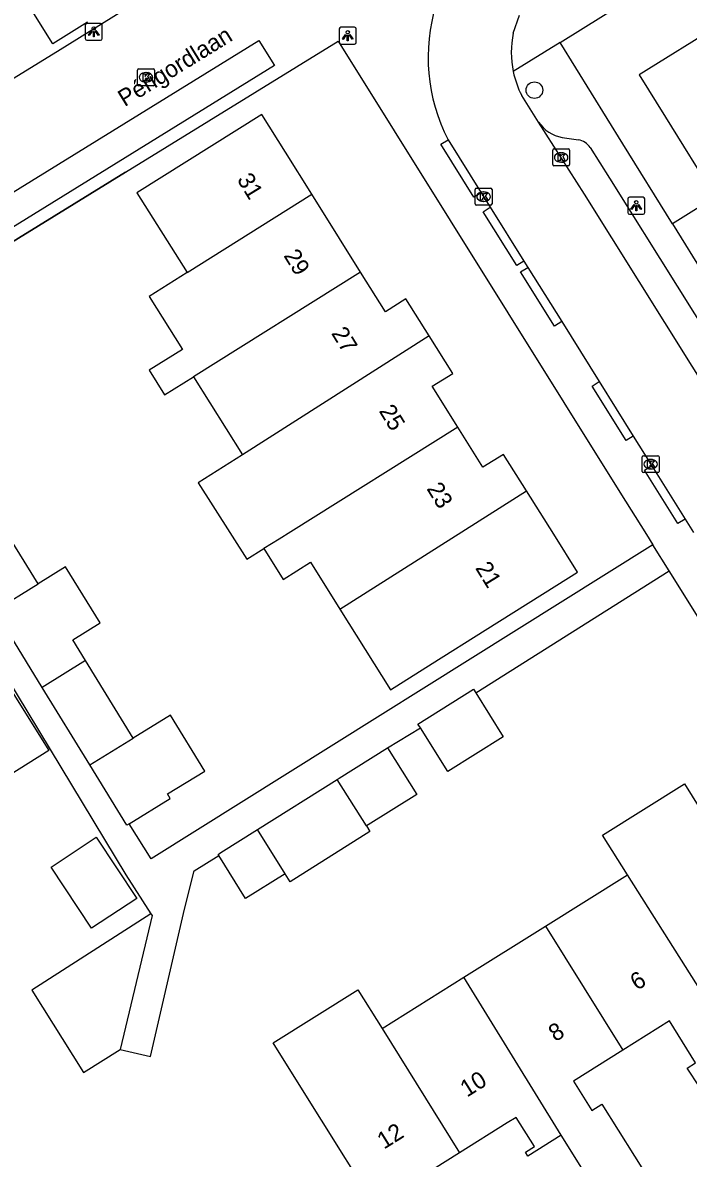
# Model space of a CAD drawing. Extents: x 157767 to 159171, y 387842 to 389425.
# Drawn here: x 158346.5 to 158385.9, y 388132.7 to 388199.8 of the extents above; entities that cross this region are included whole.
import ezdxf

# ---------------------------------------------------------------- set-up
doc = ezdxf.new("R2010")
doc.units = 0
for name, color, linetype in [('IMGEO_Boom', 7, 'Continuous'), ('IMGEO_Kolk', 7, 'Continuous'), ('IMGEO_Lichtpunt', 7, 'Continuous'), ('IMGEO_Muur', 7, 'Continuous'), ('IMGEO_Openbare_ruimte_label', 7, 'Continuous'), ('IMGEO_Pand', 7, 'Continuous'), ('IMGEO_Pand_nummerreeks', 7, 'Continuous'), ('IMGEO_Rijbaan_lokaal_open', 7, 'Continuous'), ('IMGEO_Voetpad_open', 7, 'Continuous')]:
    doc.layers.add(name, color=color, linetype=linetype)

msp = doc.modelspace()

# ---------------------------------------------------------------- linework, layer by layer
at = {"layer": 'IMGEO_Boom'}
msp.add_circle((158376.764, 388195.808), 0.489, dxfattribs=at)
at = {"layer": 'IMGEO_Kolk'}
for p, q in [((158353.327, 388196.137), (158353.327, 388196.989)), ((158353.402, 388197.063), (158354.254, 388197.063)), ((158354.328, 388196.989), (158354.328, 388196.137)), ((158353.838, 388196.283), (158353.813, 388196.283)), ((158353.815, 388196.843), (158353.84, 388196.843)), ((158354.254, 388196.063), (158353.402, 388196.063)), ((158377.846, 388191.409), (158377.846, 388192.261)), ((158377.921, 388192.335), (158378.773, 388192.335)), ((158378.847, 388192.261), (158378.847, 388191.409)), ((158378.357, 388191.555), (158378.332, 388191.555)), ((158378.334, 388192.115), (158378.359, 388192.115)), ((158378.773, 388191.335), (158377.921, 388191.335)), ((158373.261, 388189.093), (158373.261, 388189.945)), ((158373.336, 388190.019), (158374.188, 388190.019)), ((158373.749, 388189.799), (158373.774, 388189.799)), ((158374.262, 388189.945), (158374.262, 388189.093)), ((158374.188, 388189.019), (158373.336, 388189.019)), ((158373.772, 388189.239), (158373.747, 388189.239)), ((158383.133, 388173.299), (158383.133, 388174.151)), ((158383.208, 388174.225), (158384.06, 388174.225)), ((158384.134, 388174.151), (158384.134, 388173.299)), ((158383.644, 388173.445), (158383.619, 388173.445)), ((158383.621, 388174.005), (158383.646, 388174.005)), ((158384.06, 388173.225), (158383.208, 388173.225))]:
    msp.add_line(p, q, dxfattribs=at)
for points in [[(158353.327, 388196.137), (158353.327, 388196.989)], [(158353.402, 388197.063), (158354.254, 388197.063)], [(158354.328, 388196.989), (158354.328, 388196.137)], [(158353.648, 388196.763), (158353.771, 388196.763), (158353.771, 388196.612), (158353.901, 388196.763), (158354.065, 388196.763), (158353.919, 388196.612), (158354.072, 388196.363), (158353.92, 388196.363), (158353.835, 388196.527), (158353.771, 388196.46), (158353.771, 388196.363), (158353.648, 388196.363), (158353.648, 388196.763)], [(158354.254, 388196.063), (158353.402, 388196.063)], [(158377.846, 388191.409), (158377.846, 388192.261)], [(158377.921, 388192.335), (158378.773, 388192.335)], [(158378.847, 388192.261), (158378.847, 388191.409)], [(158378.167, 388192.035), (158378.29, 388192.035), (158378.29, 388191.884), (158378.42, 388192.035), (158378.584, 388192.035), (158378.438, 388191.884), (158378.591, 388191.635), (158378.439, 388191.635), (158378.354, 388191.799), (158378.29, 388191.732), (158378.29, 388191.635), (158378.167, 388191.635), (158378.167, 388192.035)], [(158378.773, 388191.335), (158377.921, 388191.335)], [(158373.261, 388189.093), (158373.261, 388189.945)], [(158373.336, 388190.019), (158374.188, 388190.019)], [(158373.582, 388189.719), (158373.705, 388189.719), (158373.705, 388189.568), (158373.835, 388189.719), (158373.999, 388189.719), (158373.853, 388189.568), (158374.006, 388189.319), (158373.854, 388189.319), (158373.769, 388189.483), (158373.705, 388189.416), (158373.705, 388189.319), (158373.582, 388189.319), (158373.582, 388189.719)], [(158374.262, 388189.945), (158374.262, 388189.093)], [(158374.188, 388189.019), (158373.336, 388189.019)], [(158383.133, 388173.299), (158383.133, 388174.151)], [(158383.208, 388174.225), (158384.06, 388174.225)], [(158384.134, 388174.151), (158384.134, 388173.299)], [(158383.454, 388173.925), (158383.577, 388173.925), (158383.577, 388173.774), (158383.707, 388173.925), (158383.871, 388173.925), (158383.725, 388173.774), (158383.878, 388173.525), (158383.726, 388173.525), (158383.641, 388173.689), (158383.577, 388173.622), (158383.577, 388173.525), (158383.454, 388173.525), (158383.454, 388173.925)], [(158384.06, 388173.225), (158383.208, 388173.225)]]:
    msp.add_lwpolyline(points, dxfattribs=at)
for centre, start, end in [((158353.404, 388196.987), 91.55205, 178.44795), ((158353.404, 388196.987), 91.55205, 178.44795), ((158354.252, 388196.987), 1.55205, 88.44795), ((158354.252, 388196.987), 1.55205, 88.44795), ((158353.404, 388196.139), 181.55205, 268.44795), ((158353.404, 388196.139), 181.55205, 268.44795), ((158354.252, 388196.139), 271.55205, 358.44795), ((158354.252, 388196.139), 271.55205, 358.44795), ((158377.923, 388192.259), 91.55205, 178.44795), ((158377.923, 388192.259), 91.55205, 178.44795), ((158378.771, 388192.259), 1.55205, 88.44795), ((158378.771, 388192.259), 1.55205, 88.44795), ((158377.923, 388191.411), 181.55205, 268.44795), ((158377.923, 388191.411), 181.55205, 268.44795), ((158378.771, 388191.411), 271.55205, 358.44795), ((158378.771, 388191.411), 271.55205, 358.44795), ((158373.338, 388189.943), 91.55205, 178.44795), ((158373.338, 388189.943), 91.55205, 178.44795), ((158374.186, 388189.943), 1.55205, 88.44795), ((158374.186, 388189.943), 1.55205, 88.44795), ((158373.338, 388189.095), 181.55205, 268.44795), ((158373.338, 388189.095), 181.55205, 268.44795), ((158374.186, 388189.095), 271.55205, 358.44795), ((158374.186, 388189.095), 271.55205, 358.44795), ((158383.21, 388174.149), 91.55205, 178.44795), ((158383.21, 388174.149), 91.55205, 178.44795), ((158384.058, 388174.149), 1.55205, 88.44795), ((158384.058, 388174.149), 1.55205, 88.44795), ((158383.21, 388173.301), 181.55205, 268.44795), ((158383.21, 388173.301), 181.55205, 268.44795), ((158384.058, 388173.301), 271.55205, 358.44795), ((158384.058, 388173.301), 271.55205, 358.44795)]:
    msp.add_arc(centre, 0.0765, start, end, dxfattribs=at)
for centre, major_axis, ratio, start_param, end_param in [((158353.814, 388196.563), (-0.387, 0.002), 0.722429, 4.712389, 7.853982), ((158353.839, 388196.563), (-0.39, 0.002), 0.717154, 1.570796, 4.712389), ((158378.333, 388191.835), (-0.387, 0.002), 0.722429, 4.712389, 7.853982), ((158378.358, 388191.835), (-0.39, 0.002), 0.717154, 1.570796, 4.712389), ((158373.748, 388189.519), (-0.387, 0.002), 0.722429, 4.712389, 7.853982), ((158373.773, 388189.519), (-0.39, 0.002), 0.717154, 1.570796, 4.712389), ((158383.62, 388173.725), (-0.387, 0.002), 0.722429, 4.712389, 7.853982), ((158383.645, 388173.725), (-0.39, 0.002), 0.717154, 1.570796, 4.712389)]:
    msp.add_ellipse(centre, major_axis=major_axis, ratio=ratio, start_param=start_param, end_param=end_param, dxfattribs=at)
at = {"layer": 'IMGEO_Lichtpunt'}
for p, q in [((158350.237, 388199.656), (158350.237, 388198.849)), ((158350.237, 388199.656), (158350.237, 388198.849)), ((158351.139, 388199.751), (158350.331, 388199.751)), ((158351.139, 388199.751), (158350.331, 388199.751)), ((158351.233, 388198.849), (158351.233, 388199.656)), ((158351.233, 388198.849), (158351.233, 388199.656)), ((158365.239, 388199.428), (158365.239, 388198.621)), ((158365.239, 388199.428), (158365.239, 388198.621)), ((158366.141, 388199.523), (158365.333, 388199.523)), ((158366.141, 388199.523), (158365.333, 388199.523)), ((158366.235, 388198.621), (158366.235, 388199.428)), ((158366.235, 388198.621), (158366.235, 388199.428)), ((158350.331, 388198.755), (158351.139, 388198.755)), ((158350.331, 388198.755), (158351.139, 388198.755)), ((158365.333, 388198.527), (158366.141, 388198.527)), ((158365.333, 388198.527), (158366.141, 388198.527)), ((158383.185, 388189.481), (158382.377, 388189.481)), ((158383.185, 388189.481), (158382.377, 388189.481)), ((158382.283, 388189.386), (158382.283, 388188.579)), ((158382.283, 388189.386), (158382.283, 388188.579)), ((158383.279, 388188.579), (158383.279, 388189.386)), ((158383.279, 388188.579), (158383.279, 388189.386)), ((158382.377, 388188.485), (158383.185, 388188.485)), ((158382.377, 388188.485), (158383.185, 388188.485))]:
    msp.add_line(p, q, dxfattribs=at)
for points in [[(158350.611, 388199.32), (158350.65, 388199.292), (158350.462, 388199.03), (158350.424, 388199.057), (158350.611, 388199.32)], [(158350.713, 388199.272), (158350.76, 388199.272), (158350.76, 388198.95), (158350.713, 388198.95), (158350.713, 388199.272)], [(158350.823, 388199.292), (158350.861, 388199.319), (158351.048, 388199.057), (158351.009, 388199.029), (158350.823, 388199.292)], [(158365.613, 388199.092), (158365.652, 388199.064), (158365.464, 388198.802), (158365.426, 388198.829), (158365.613, 388199.092)], [(158365.715, 388199.044), (158365.762, 388199.044), (158365.762, 388198.722), (158365.715, 388198.722), (158365.715, 388199.044)], [(158365.825, 388199.064), (158365.863, 388199.091), (158366.05, 388198.829), (158366.011, 388198.801), (158365.825, 388199.064)], [(158382.657, 388189.05), (158382.696, 388189.022), (158382.508, 388188.76), (158382.47, 388188.787), (158382.657, 388189.05)], [(158382.759, 388189.002), (158382.806, 388189.002), (158382.806, 388188.68), (158382.759, 388188.68), (158382.759, 388189.002)], [(158382.869, 388189.022), (158382.907, 388189.049), (158383.094, 388188.787), (158383.055, 388188.759), (158382.869, 388189.022)]]:
    msp.add_lwpolyline(points, dxfattribs=at)
for centre in [(158350.736, 388199.454), (158365.738, 388199.226), (158382.782, 388189.184)]:
    msp.add_circle(centre, 0.0994, dxfattribs=at)
for centre, start, end in [((158350.331, 388199.656), 90, 180), ((158350.331, 388199.656), 90, 180), ((158351.139, 388199.656), 0, 90), ((158351.139, 388199.656), 0, 90), ((158365.333, 388199.428), 90, 180), ((158365.333, 388199.428), 90, 180), ((158366.141, 388199.428), 0, 90), ((158366.141, 388199.428), 0, 90), ((158350.331, 388198.849), 180, 270), ((158350.331, 388198.849), 180, 270), ((158351.139, 388198.849), 270, 0), ((158351.139, 388198.849), 270, 360), ((158365.333, 388198.621), 180, 270), ((158365.333, 388198.621), 180, 270), ((158366.141, 388198.621), 270, 0), ((158366.141, 388198.621), 270, 360), ((158382.377, 388189.386), 90, 180), ((158382.377, 388189.386), 90, 180), ((158383.185, 388189.386), 0, 90), ((158383.185, 388189.386), 0, 90), ((158382.377, 388188.579), 180, 270), ((158382.377, 388188.579), 180, 270), ((158383.185, 388188.579), 270, 0), ((158383.185, 388188.579), 270, 360)]:
    msp.add_arc(centre, 0.0946, start, end, dxfattribs=at)
at = {"layer": 'IMGEO_Muur'}
msp.add_lwpolyline([(158352.615, 388190.965), (158339.034, 388182.597)], dxfattribs=at)
at = {"layer": 'IMGEO_Pand'}
for points in [[(158350.367, 388199.826), (158348.327, 388198.55), (158345.621, 388202.878), (158347.67, 388204.159)], [(158387.786, 388199.708), (158382.96, 388196.71), (158384.517, 388194.205), (158387.451, 388189.482), (158384.92, 388187.91)], [(158363.613, 388189.658), (158362.055, 388192.14), (158360.657, 388194.368), (158353.291, 388189.745), (158356.247, 388185.035)], [(158356.247, 388185.035), (158363.613, 388189.658)], [(158366.494, 388185.067), (158365.255, 388187.041), (158363.613, 388189.658)], [(158384.92, 388187.91), (158386.867, 388184.775)], [(158356.247, 388185.035), (158354.01, 388183.631), (158355.974, 388180.502), (158354.007, 388179.267), (158354.921, 388177.811), (158356.63, 388178.887)], [(158366.494, 388185.067), (158356.63, 388178.887)], [(158370.552, 388181.294), (158369.175, 388183.487), (158367.963, 388182.726), (158366.494, 388185.067)], [(158370.552, 388181.294), (158359.517, 388174.286)], [(158372.239, 388175.915), (158370.728, 388178.322), (158371.94, 388179.083), (158370.552, 388181.294)], [(158356.63, 388178.887), (158359.517, 388174.286)], [(158372.239, 388175.915), (158362.373, 388169.736), (158361.686, 388169.306), (158360.781, 388168.739)], [(158376.293, 388172.15), (158374.939, 388174.306), (158373.727, 388173.545), (158372.239, 388175.915)], [(158359.517, 388174.286), (158356.909, 388172.63), (158359.778, 388168.111), (158360.781, 388168.739)], [(158365.273, 388165.174), (158376.293, 388172.15)], [(158365.273, 388165.174), (158368.264, 388160.41), (158370.732, 388161.959), (158373.863, 388163.924), (158378.097, 388166.582), (158379.311, 388167.344), (158377.905, 388169.584), (158376.293, 388172.15)], [(158347.446, 388166.668), (158345.292, 388170.164), (158342.735, 388168.588)], [(158360.781, 388168.739), (158361.926, 388166.916), (158363.543, 388167.931), (158365.273, 388165.174)], [(158350.241, 388162.135), (158349.493, 388163.347), (158351.12, 388164.35), (158349.073, 388167.671), (158347.446, 388166.668)], [(158344.889, 388165.093), (158347.446, 388166.668)], [(158347.695, 388160.541), (158344.889, 388165.093)], [(158350.241, 388162.135), (158347.695, 388160.541)], [(158353.069, 388157.546), (158350.241, 388162.135)], [(158345.095, 388154.958), (158342.281, 388159.457), (158345.275, 388161.329), (158348.089, 388156.83), (158345.095, 388154.958)], [(158350.513, 388155.97), (158347.695, 388160.541)], [(158370.028, 388158.152), (158369.887, 388158.377), (158373.161, 388160.432), (158373.297, 388160.216)], [(158373.297, 388160.216), (158374.919, 388157.63), (158371.645, 388155.576), (158370.028, 388158.152)], [(158352.825, 388152.496), (158355.258, 388153.995), (158355.098, 388154.254), (158357.294, 388155.608), (158355.265, 388158.899), (158353.069, 388157.546)], [(158350.513, 388155.97), (158353.069, 388157.546)], [(158365.122, 388155.108), (158365.234, 388155.178), (158368.095, 388156.973)], [(158368.095, 388156.973), (158369.816, 388154.23), (158366.955, 388152.435), (158366.843, 388152.365)], [(158352.825, 388152.496), (158352.701, 388152.42), (158350.513, 388155.97)], [(158360.402, 388152.147), (158365.122, 388155.108)], [(158366.843, 388152.365), (158365.122, 388155.108)], [(158382.257, 388149.489), (158380.796, 388151.819), (158385.624, 388154.847), (158387.085, 388152.518)], [(158358.116, 388150.629), (158358.079, 388150.689), (158358.252, 388150.798), (158360.402, 388152.147)], [(158362.034, 388149.546), (158360.402, 388152.147)], [(158366.843, 388152.365), (158367.051, 388152.035), (158362.33, 388149.073), (158362.034, 388149.546)], [(158348.218, 388149.928), (158350.885, 388151.698), (158353.282, 388148.084), (158350.604, 388146.331), (158348.218, 388149.928)], [(158362.034, 388149.546), (158359.71, 388148.089), (158358.116, 388150.629)], [(158377.424, 388146.458), (158382.257, 388149.489)], [(158388.122, 388140.218), (158382.257, 388149.489)], [(158354.112, 388147.172), (158347.087, 388142.674), (158350.141, 388137.811), (158352.303, 388139.169)], [(158354.112, 388147.172), (158354.179, 388147.082), (158352.303, 388139.169)], [(158372.598, 388143.43), (158377.424, 388146.458)], [(158377.424, 388146.458), (158381.98, 388139.128)], [(158367.77, 388140.402), (158372.598, 388143.43)], [(158378.348, 388134.112), (158372.598, 388143.43)], [(158367.804, 388127.623), (158368.545, 388128.049), (158362.775, 388137.268), (158361.338, 388139.558), (158366.333, 388142.692), (158367.77, 388140.402)], [(158393.468, 388131.678), (158391.387, 388130.374), (158388.715, 388134.638), (158387.745, 388136.187), (158387.237, 388135.869), (158385.779, 388138.072), (158386.287, 388138.39), (158384.743, 388140.857), (158381.98, 388139.128)], [(158367.77, 388140.402), (158372.331, 388133.064)], [(158381.98, 388139.128), (158379.07, 388137.305), (158380.155, 388135.573), (158380.748, 388135.945), (158383.637, 388131.335), (158383.344, 388131.151), (158383.018, 388130.947)], [(158378.348, 388134.112), (158376.38, 388132.88), (158376.236, 388133.109), (158376.762, 388133.438), (158375.682, 388135.162), (158375.157, 388134.833), (158372.331, 388133.064)], [(158381.049, 388129.801), (158378.348, 388134.112)], [(158372.331, 388133.064), (158369.427, 388131.246), (158368.902, 388130.918), (158370.027, 388129.121), (158370.552, 388129.449), (158373.314, 388125.035), (158375.996, 388120.749), (158373.127, 388118.954), (158371.859, 388120.98)]]:
    msp.add_lwpolyline(points, dxfattribs=at)
at = {"layer": 'IMGEO_Rijbaan_lokaal_open'}
for points in [[(158331.025, 388187.169), (158333.092, 388188.466), (158338.88, 388192.098), (158342.746, 388194.533), (158348.606, 388198.107), (158352.487, 388200.522), (158355.385, 388202.255), (158355.501, 388202.324), (158354.496, 388203.976), (158373.677, 388216.222)], [(158375.518, 388199.174), (158375.884, 388200.241)], [(158339.034, 388182.597), (158352.615, 388190.965), (158365.167, 388198.706), (158381.815, 388172.081), (158383.379, 388169.579), (158383.764, 388168.963)], [(158340.911, 388184.618), (158339.992, 388186.111), (158360.492, 388198.747), (158361.412, 388197.254), (158340.911, 388184.618)], [(158377.015, 388193.922), (158376.014, 388195.494)], [(158390.443, 388172.459), (158387.701, 388176.941), (158379.723, 388189.672), (158377.015, 388193.922)], [(158373.62, 388189.751), (158373.197, 388189.486), (158371.24, 388192.617), (158371.663, 388192.882)], [(158371.663, 388192.882), (158373.62, 388189.751)], [(158373.62, 388189.751), (158374.157, 388188.891)], [(158376.148, 388185.705), (158375.721, 388185.446), (158373.73, 388188.632), (158374.157, 388188.891)], [(158374.157, 388188.891), (158376.148, 388185.705)], [(158376.148, 388185.705), (158376.377, 388185.339)], [(158378.377, 388182.139), (158377.95, 388181.88), (158375.95, 388185.08), (158376.377, 388185.339)], [(158376.377, 388185.339), (158378.377, 388182.139)], [(158378.377, 388182.139), (158380.591, 388178.597)], [(158382.599, 388175.383), (158382.175, 388175.119), (158380.167, 388178.333), (158380.591, 388178.597)], [(158380.591, 388178.597), (158382.599, 388175.383)], [(158382.599, 388175.383), (158383.692, 388173.634)], [(158385.662, 388170.483), (158385.235, 388170.224), (158383.265, 388173.375), (158383.692, 388173.634)], [(158383.692, 388173.634), (158385.662, 388170.483)], [(158385.662, 388170.483), (158386.156, 388169.693)], [(158384.722, 388167.431), (158383.764, 388168.963)], [(158392.004, 388155.561), (158392.121, 388155.599), (158384.722, 388167.431)]]:
    msp.add_lwpolyline(points, dxfattribs=at)
for centre, radius, start, end in [((158381.143, 388197.749), 10.656, 163.04225, 207.17557), ((158381.016, 388198.036), 5.614, 168.30644, 191.6431), ((158380.975, 388198.036), 5.574, 191.72783, 207.13097)]:
    msp.add_arc(centre, radius, start, end, dxfattribs=at)
at = {"layer": 'IMGEO_Voetpad_open'}
for points in [[(158378.277, 388198.624), (158417.818, 388223.257)], [(158378.277, 388198.624), (158375.517, 388196.903)], [(158384.92, 388187.91), (158381.986, 388192.633), (158378.277, 388198.624)], [(158378.398, 388193.02), (158379.366, 388192.871)], [(158380.057, 388192.42), (158381.209, 388190.611), (158389.196, 388177.866), (158390.132, 388176.336)], [(158383.764, 388168.963), (158354.129, 388150.416), (158352.825, 388152.496)], [(158373.297, 388160.216), (158384.722, 388167.431)], [(158342.348, 388166.462), (158352.638, 388149.483), (158354.112, 388147.172)], [(158368.095, 388156.973), (158370.028, 388158.152)], [(158352.303, 388139.169), (158354.084, 388138.756), (158356.101, 388147.452), (158356.667, 388149.714), (158358.116, 388150.629)]]:
    msp.add_lwpolyline(points, dxfattribs=at)
for centre, radius, start, end in [((158378.764, 388195.093), 2.105, 213.79839, 259.9764), ((158379.213, 388191.881), 1.002, 32.54978, 81.18708)]:
    msp.add_arc(centre, radius, start, end, dxfattribs=at)

# ---------------------------------------------------------------- texts
at = {"layer": 'IMGEO_Openbare_ruimte_label'}
msp.add_text('Périgordlaan', height=1, rotation=31.67132, dxfattribs=at).set_placement((158352.563, 388194.799))
at = {"layer": 'IMGEO_Pand_nummerreeks'}
for s, rotation, p in [('31', 301.53927, (158359.17, 388190.53)), ('29', 301.53927, (158361.927, 388186.039)), ('27', 301.53927, (158364.742, 388181.453)), ('25', 301.54112, (158367.557, 388176.866)), ('23', 301.54112, (158370.372, 388172.279)), ('21', 301.54112, (158373.246, 388167.596)), ('6', 32.11082, (158382.823, 388142.624)), ('8', 32.11082, (158378, 388139.597)), ('10', 32.11082, (158372.784, 388136.323)), ('12', 32.04486, (158367.88, 388133.251))]:
    msp.add_text(s, height=1, rotation=rotation, dxfattribs=at).set_placement(p)

doc.saveas('drawing.dxf')
